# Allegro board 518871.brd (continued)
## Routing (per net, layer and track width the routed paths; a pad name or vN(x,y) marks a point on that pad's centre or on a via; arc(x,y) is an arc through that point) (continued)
H_DISPLAY_RSTN: length 40.9
  TOP w0.102: U27.Y4 55.68,86.9 55.68,90.58
  TOP w0.127: v1(85.69,95.12) 85.69,94.7 R444.1 ; v1(55.68,92.2) 55.68,90.58
  LY4 w0.133: v1(85.69,95.12) 85.69,94.58 85.22,94.11 78.11,94.11 77.85,93.85 75.82,93.85 75.18,94.49 70.87,94.49 68.83,92.46 64.9,92.46 64.64,92.2 v1(55.68,92.2)
  BOTTOM w0.127: v1(85.69,95.12) 85.69,96.65
H_DS90C189_RSTN: length 48.3
  TOP w0.127: U27.L3 v3(56.35,81.07) ; v1(97.66,87.38) R443.1
  LY3 w0.102: v3(56.35,81.07) 58.09,81.07
  LY3 w0.133: v1(97.66,87.38) 96.65,86.36 96.65,84.71 94.11,82.17 85.85,82.17 85.6,81.92 84.11,81.92 82.98,80.78 74.83,80.78 74.69,80.64 62.74,80.64 62.36,80.26 61.85,80.26 61.04,81.07 58.09,81.07
  BOTTOM w0.127: v1(97.66,87.38) 97.63,87.34 U77.52
H_EMU0: length 50.7
  TOP w0.102: 44.33,75.54 U27.C21
  TOP w0.127: v3(44,75.87) 44.33,75.54 ; v1(74.68,53.85) 74.25,53.42 J14.19
  LY3 w0.133: v3(44,75.87) 44.58,75.3 44.58,73.79 45.21,73.15 45.21,68.2 48.9,64.52 48.9,62.87 51.94,59.82 v1(51.94,59.44)
  LY4 w0.133: v1(51.94,59.44) 54.86,59.44 55.24,59.05 57.4,59.05 58.04,58.42 58.8,58.42 59.44,59.05 68.07,59.05 70.74,56.39 72.9,56.39 74.68,54.61 v1(74.68,53.85)
  BOTTOM w0.127: R310.2 75.18,52.83 75.18,53.34 v1(74.68,53.85)
H_EMU1: length 48.9
  TOP w0.102: 43.68,75.54 U27.C22
  TOP w0.127: v3(44,75.22) 43.68,75.54 ; J14.21 v1(73.75,53.09)
  LY3 w0.133: v1(51.98,58.29) 51.98,58.76 48.51,62.23 48.51,64.52 46.23,66.8 44.83,66.8 44,67.63 v3(44,75.22)
  LY4 w0.133: v1(51.98,58.29) 53.74,56.53 60.73,56.53 61.47,57.28 62.1,57.28 62.65,56.73 68.37,56.73 69.85,55.24 72.26,55.24 73.28,54.23 73.28,53.56 v1(73.75,53.09)
  BOTTOM w0.127: v1(73.75,53.09) 73.53,52.87 R311.2
H_EMU2: length 30.2
  TOP w0.127: v1(75.75,53.13) J14.13
  LY4 w0.133: v1(75.75,53.13) 75.75,53.14 75.18,53.71 75.18,54.61 72.64,57.15 70.61,57.15 68.24,59.52 v1(56.05,59.52)
  BOTTOM w0.127: R292.2 54.61,64.26 55.63,63.25 55.63,62.48 56.05,62.06 v1(56.05,59.52)
H_EMU3: length 47.7
  TOP w0.127: v1(48.64,67.44) 48.19,67.88 48.19,71.16 48.77,71.73 48.77,73.91 48.57,74.11 48.57,75.64 48.11,76.09 48.11,76.73 48.88,77.49 U27.F14 ; J14.17 v1(74.75,53.09)
  LY3 w0.133: v1(48.64,67.44) 48.64,65.41 49.4,64.64 49.4,63.12 52.32,60.2 54.36,60.2 v1(56.01,58.55)
  LY4 w0.133: v1(74.75,53.09) 74.21,53.63 74.21,54.14 74.21,54.15 74.21,54.31 72.52,56.01 70.48,56.01 67.78,58.72 59.86,58.72 59.18,58.04 57.66,58.04 57.15,58.55 v1(56.01,58.55)
H_EMU4: length 47.2
  TOP w0.102: 49.28,73.51 49.28,74.04 49.23,74.09 49.23,77.17 49.53,77.47 U27.F13
  TOP w0.127: J14.23 73.25,53.31 v1(73.79,53.85) ; v1(54.95,57.02) 54.74,57.24 54.74,63.12 51.94,65.91 50.8,65.91 49.53,67.18 49.53,67.69 49.28,67.95 49.28,73.51
  LY4 w0.133: v1(54.95,57.02) 60.61,57.02 61.38,57.78 67.94,57.78 70.1,55.63 72.39,55.63 73.79,54.23 v1(73.79,53.85)
H_EMU5: length 36.9
  TOP w0.127: U27.D8 v3(52.45,75.87) ; J14.25 v1(72.75,53.07)
  LY3 w0.133: v1(63.37,57.15) 62.74,57.78 61.72,57.78 59.31,60.2 59.31,66.42 55.17,70.56 55.17,71.45 52.83,73.79 52.83,75.49 v3(52.45,75.87)
  BOTTOM w0.127: v1(63.37,57.15) 63.88,56.64 69.17,56.64 v1(72.75,53.07)
H_EMU6: length 36.4
  TOP w0.102: U27.B7 53.75,74.57 53.75,73.51
  TOP w0.127: J14.27 72.25,53.33 v1(72.77,53.85) ; 53.75,73.51 53.75,73.14 57.15,69.74 57.15,68.58 60.58,65.15 60.58,59.94 61.47,59.06 61.47,57.66 61.72,57.4 v1(61.72,56.73)
  LY4 w0.133: v1(72.77,53.85) 71.75,54.86 69.47,54.86 67.94,56.39 62.06,56.39 v1(61.72,56.73)
H_EMU7: length 37.5
  TOP w0.127: J14.29 71.75,58.92 72.01,59.18 72.01,61.98 72.14,62.1 72.14,65.28 v1(71.63,65.79) ; U27.C7 v3(53.75,75.22)
  LY3 w0.133: v3(53.75,75.22) 53.76,74.13 59.05,68.83 59.69,68.83 62.74,65.79 v1(71.63,65.79)
H_EMU8: length 39.4
  TOP w0.127: J14.31 71.25,52.96 71.37,53.09 71.37,59.18 71.59,59.4 v1(71.59,64.77) ; v3(52.45,76.52) U27.E8
  LY3 w0.133: v1(71.59,64.77) 61.59,64.77 55.43,70.93 55.43,71.57 53.09,73.91 53.09,75.89 v3(52.45,76.52)
H_EMU9: length 34.5
  TOP w0.102: 53.1,73.51 53.1,74.57 U27.B8
  TOP w0.127: J14.33 70.75,52.93 70.74,52.95 v1(70.74,53.09) ; v1(60.45,58.29) 60.07,58.67 60.07,64.9 56.64,68.33 56.64,69.53 53.1,73.07 53.1,73.51
  BOTTOM w0.127: v1(70.74,53.09) 70.74,54.23 68.71,56.26 63.5,56.26 61.98,57.78 60.96,57.78 v1(60.45,58.29)
H_EMU10: length 35.5
  TOP w0.127: v1(70.25,53.85) J14.35 ; v3(52.45,75.22) 52.78,75.54 U27.C8
  LY3 w0.133: v1(59.73,57.53) 59.73,59.02 58.93,59.82 58.93,66.29 54.91,70.31 54.91,71.33 52.45,73.78 v3(52.45,75.22)
  BOTTOM w0.127: v1(70.25,53.85) 69.49,54.61 66.04,54.61 65.15,55.5 61.76,55.5 v1(59.73,57.53)
H_EMU11: length 35.6
  TOP w0.102: 52.45,73.51 52.45,74.57 U27.B9
  TOP w0.127: J14.37 v1(69.75,53.09) ; v1(59.82,56.11) 59.82,56.13 59.31,56.64 59.31,64.9 56.13,68.07 56.13,69.09 54.75,70.47 54.03,70.47 53.84,70.67 53.84,71.39 52.45,72.77 52.45,73.51
  BOTTOM w0.127: v1(59.82,56.11) 59.84,56.11 61.13,54.82 64.05,54.82 64.77,54.1 69.47,54.1 69.75,53.82 v1(69.75,53.09)
H_EMU12: length 33.7
  TOP w0.127: v1(62.87,53.09) 62.87,54.61 61.09,56.39 61.09,58.93 60.33,59.69 60.33,65.02 56.9,68.45 56.9,69.64 53.43,73.1 U27.A7 ; J14.39 v1(69.25,53.59)
  BOTTOM w0.127: v1(62.87,53.09) 63.37,53.59 v1(69.25,53.59)
H_EMU13: length 34.4
  TOP w0.127: U27.A9 52.13,72.53 52.83,71.83 52.83,70.87 53.48,70.22 54.14,70.22 55.5,68.86 55.5,68.33 58.97,64.86 v1(58.97,56.11) ; J14.41 v1(68.75,53.09)
  BOTTOM w0.127: v1(68.75,53.09) 68.24,52.58 62.48,52.58 58.97,56.1 v1(58.97,56.11)
H_EMU14: length 36.1
  TOP w0.127: J14.43 v1(68.25,49.28) ; v1(61.09,53.17) 61.09,55.12 60.71,55.5 60.71,57.36 59.69,58.38 59.69,64.88 56.39,68.18 56.39,69.42 52.78,73.03 U27.A8
  BOTTOM w0.127: v1(61.09,53.17) 62.06,52.2 66.29,52.2 68.25,50.24 v1(68.25,49.28)
H_EMU15: length 36.5
  TOP w0.127: v1(57.75,56.11) 57.28,56.58 57.28,63.25 52.58,67.94 52.58,68.71 52.32,68.96 50.93,68.96 50.55,69.34 50.55,71.4 50.83,71.68 U27.A11 ; J14.45 v1(67.75,49.91)
  BOTTOM w0.127: v1(57.75,56.11) 60.45,53.41 60.45,52.96 61.59,51.82 65.91,51.82 67.75,49.98 v1(67.75,49.91)
H_EMU16: length 40.3
  TOP w0.127: J14.47 v1(67.25,49.28) ; U27.F10 v3(51.15,77.17)
  LY3 w0.133: v1(56.1,62.74) 56.1,66.71 54.74,68.07 54.74,68.83 52.7,70.87 52.7,71.25 51.43,72.52 51.43,74.31 51.18,74.56 51.18,77.14 51.18,77.14 v3(51.15,77.17)
  BOTTOM w0.127: v1(56.1,62.74) 57.28,61.56 57.28,53.98 60.33,50.93 65.02,50.93 66.67,49.28 v1(67.25,49.28)
H_EMU17: length 35.2
  TOP w0.127: J14.49 v1(66.75,49.91) ; v1(59.94,53.09) 59.94,54.36 58.55,55.75 58.55,56.68 58.04,57.19 58.04,65.02 54.81,68.25 54.81,68.73 53.83,69.71 53.69,69.71 52.86,69.71 51.73,70.83 51.73,72.09 51.48,72.35 U27.A10
  BOTTOM w0.127: v1(66.75,49.91) 65.23,51.44 61.15,51.44 59.94,52.64 v1(59.94,53.09)
H_EMU18: length 32.4
  TOP w0.102: U27.B10 51.81,74.57 51.81,73.51
  TOP w0.127: v1(58.47,58.93) 58.47,64.98 55.17,68.27 55.17,68.73 53.94,69.96 53.59,69.96 53.58,69.96 53.23,69.96 52.58,70.61 52.58,71.62 51.81,72.39 51.81,73.51 ; v1(66.25,55.33) J14.51
  BOTTOM w0.127: v1(58.47,58.93) 59.14,58.93 60.66,57.4 61.72,57.4 63.25,55.88 65.7,55.88 v1(66.25,55.33)
H_EMU19: length 33.8
  TOP w0.127: v1(65.02,54.86) 65.75,54.14 J14.53 ; U27.E10 v3(51.8,76.52)
  LY3 w0.133: v3(51.8,76.52) 51.42,76.13 51.42,74.96 51.82,74.56 51.82,73.28 53.85,71.25 53.85,70.1 57.78,66.17 57.78,58.8 58.55,58.04 v1(58.55,57.49)
  BOTTOM w0.127: v1(58.55,57.49) 59.14,56.9 59.82,56.9 61.59,55.12 64.77,55.12 v1(65.02,54.86)
H_HDMI_CLKX: length 32.6
  TOP w0.112: U27.AE9 52.13,90.11 53.95,91.93 53.95,104.37 50.47,107.85 46.74,107.85 45.49,109.09 42.22,109.09 42.09,109.22 42.09,109.5 41.96,109.63 41.77,109.63 41.64,109.5 41.64,109.22 41.51,109.09 40.8,109.09 40.67,109.23 40.67,109.55 40.92,109.81 FL4.4
H_HDMI_CLKY: length 32.6
  TOP w0.112: U27.AD10 51.77,89.49 51.77,90.26 53.59,92.08 53.59,104.22 50.32,107.49 46.59,107.49 45.34,108.74 40.66,108.74 40.31,109.08 40.31,109.6 40.11,109.81 FL4.1
H_HDMI_DX0: length 31.2
  TOP w0.112: FL8.4 37.87,108.1 37.64,107.87 37.64,107.43 37.75,107.31 39.6,107.31 39.73,107.45 39.73,107.72 39.86,107.85 40.04,107.85 40.17,107.72 40.17,107.45 40.31,107.31 44.78,107.31 45.89,106.2 48.92,106.2 51.44,103.68 51.44,91.57 50.84,90.98 50.84,90.43 50.83,90.42 U27.AE11
H_HDMI_DX1: length 32
  TOP w0.102: 50.18,90.58 50.18,90.55 50.18,90.55 U27.AE12
  TOP w0.112: 50.18,90.58 50.18,92.09 50.42,92.33 50.42,98.83 43.33,105.92 33.91,105.92 33.66,106.17 33.66,106.73 33.79,106.86 34.05,106.86 34.16,106.97 34.16,107.2 34.05,107.31 33.69,107.31 33.58,107.42 33.58,107.87 33.81,108.1 FL7.4
H_HDMI_DX2: length 35
  TOP w0.102: 48.94,90.7 48.94,90.63 48.94,90.53 48.88,90.47 U27.AE14
  TOP w0.112: FL3.4 30.76,110.13 30.53,109.91 30.53,109.63 30.64,109.52 31,109.52 31.11,109.41 31.11,109.18 31,109.07 30.72,109.07 30.61,108.96 30.61,106.3 32.38,104.52 42.44,104.52 48.96,98 48.96,90.97 48.96,90.72 48.94,90.71 48.94,90.7
H_HDMI_DY0: length 31.3
  TOP w0.102: U27.AD12 50.48,89.5 50.48,90.58
  TOP w0.112: 50.48,90.58 50.48,91.13 51.08,91.72 51.08,103.54 48.77,105.84 45.75,105.84 44.63,106.96 37.61,106.96 37.29,107.28 37.29,107.87 37.06,108.1 FL8.1
H_HDMI_DY1: length 32
  TOP w0.102: 49.82,90.58 49.82,90.55 49.82,90.55 49.82,89.48 U27.AD13
  TOP w0.112: 49.82,90.58 49.82,92.24 50.06,92.48 50.06,98.68 43.19,105.56 33.76,105.56 33.3,106.02 33.3,106.87 33.22,106.95 33.22,107.87 32.99,108.1 FL7.1
H_HDMI_DY2: length 35
  TOP w0.102: U27.AD15 48.56,89.52 48.56,89.99 48.65,90.09 48.65,90.47 48.6,90.52 48.6,90.63 48.6,90.83 48.6,90.87
  TOP w0.112: 48.6,90.87 48.6,90.95 48.6,90.97 48.6,97.85 42.29,104.17 32.24,104.17 30.25,106.15 30.25,109.11 30.18,109.18 30.18,109.91 29.95,110.13 FL3.1
H_I2C1_SCL: length 277.1
  TOP w0.127: U602.5 39.87,49.27 v1(39.62,49.02) ; v1(11.56,111.51) U22.6 ; U78.19 24.36,54.08 24.64,54.36 24.89,54.36 v1(25.4,54.86) 25.4,61.34 25.15,61.59 v1(25.15,65.02) ; U27.G22 v3(43.35,77.82) ; U26.6 v1(48.01,122.42) ; U606.16 v1(123.32,112.91)
  LY4 w0.133: v1(123.32,112.91) 120.78,110.37 120.78,108.08 119,106.3 116.33,106.3 115.06,105.03 78.23,105.03 73.03,110.24 73.03,116.46 71.12,118.36 61.59,118.36 54.99,124.97 52.7,124.97 50.16,122.42 v1(48.01,122.42) 47.49,122.94 27.69,122.94 20.95,116.2 13.97,116.2 10.92,113.16 10.92,112.14 v1(11.56,111.51) 12.06,111 12.06,109.35 1.87,99.16 1.87,68.1 4.95,65.02 v1(25.15,65.02) 27.56,65.02 35.16,72.62 36.92,72.62 38.18,73.88 39.42,73.88 v3(43.35,77.82) ; v1(39.62,49.02) 37.51,49.02 37.16,49.37 37.16,50.12 37.59,50.55 37.59,57.78 36.84,58.54 29.08,58.54 v1(25.4,54.86)
  BOTTOM w0.127: R234.1 v1(11.56,111.51)
H_I2C1_SDA: length 277.2
  TOP w0.102: U27.G23 42.73,77.84 40.97,77.84
  TOP w0.127: v1(24.64,65.66) 24.64,54.91 v1(24.62,54.89) 23.86,54.13 U78.20 ; U602.6 v1(40.37,49.03) ; U606.15 v1(123.32,112.11) ; 40.97,77.84 40.12,77.84 38.73,76.45 36.07,76.45 31.11,71.5 v1(31.11,70.23) ; U22.5 v1(11.56,112.78) ; v1(47.24,122.43) 47.74,122.92 U26.5
  LY4 w0.133: v1(40.37,49.03) 39.79,48.45 37.53,48.45 36.83,49.15 36.83,50.42 37.08,50.67 37.08,54.1 34.54,56.64 34.54,57.66 34.04,58.17 29.84,58.17 26.04,54.36 25.15,54.36 v1(24.62,54.89) ; v1(31.11,70.23) 26.54,65.66 v1(24.64,65.66) 5.33,65.66 5.21,65.78 4.71,65.78 2.13,68.35 2.13,98.91 12.57,109.35 12.57,111.76 v1(11.56,112.78) 14.61,115.82 21.21,115.82 27.81,122.43 v1(47.24,122.43) 48.26,121.41 49.78,121.41 52.96,124.59 54.74,124.59 61.34,117.98 70.87,117.98 72.64,116.2 72.64,109.86 77.98,104.52 115.32,104.52 116.59,105.79 119.13,105.79 121.28,107.95 121.28,110.08 v1(123.32,112.11)
  BOTTOM w0.127: v1(11.56,112.78) R233.1
H_JTAG_RTCK: length 71.4
  TOP w0.127: v1(26.42,62.48) 26.42,70.99 R70.2 ; J14.7 77.25,53.37 v1(77.72,53.85)
  LY4 w0.133: v1(77.72,53.85) 77.72,53.98 72.26,59.44 69.6,59.44 68.71,60.33 49.53,60.33 48.64,61.21 27.69,61.21 v1(26.42,62.48)
H_JTAG_TCK: length 63.1
  TOP w0.127: v1(78.49,53.47) 78.49,53.09 78.25,52.85 J14.3 ; v3(44,79.77) U27.K21
  LY3 w0.133: v1(53.47,53.47) 51.56,55.37 51.56,58.55 48.13,61.98 48.13,64.39 46.48,66.04 43.69,66.04 43.05,66.67 43.05,74.42 42.8,74.68 42.8,78.56 v3(44,79.77)
  LY4 w0.133: v1(78.49,53.47) 78.49,53.09 77.85,52.45 54.48,52.45 v1(53.47,53.47)
  BOTTOM w0.127: R307.2 v1(78.49,53.47)
H_JTAG_TDI: length 90
  TOP w0.102: 40.97,80.77 41.15,80.77 41.42,81.04 42.73,81.04 U27.L23
  TOP w0.127: 40.97,80.77 39.37,80.77 38.1,79.5 35.03,79.5 31.98,76.45 27.81,76.45 25.78,74.42 v1(25.78,61.98) ; J14.5 v1(77.75,53.09)
  LY4 w0.133: v1(77.75,53.09) 77.3,53.53 77.3,53.89 72.14,59.05 69.34,59.05 68.45,59.94 49.28,59.94 48.39,60.83 26.92,60.83 v1(25.78,61.98)
H_JTAG_TDO: length 62.4
  TOP w0.127: J14.4 78.25,44.22 v1(78.99,43.47)
  LY3 w0.133: v1(31.75,65.79) 32.63,64.9 44.19,64.9 50.79,58.31 50.79,54.24 v1(51.94,53.09)
  BOTTOM w0.127: R264.2 v1(31.75,65.79) ; v1(51.94,53.09) 52.96,52.07 53.59,52.07 58.17,47.5 70.87,47.5 74.89,43.47 v1(78.99,43.47)
H_JTAG_TMS: length 88.8
  TOP w0.127: v1(78.99,44.2) 78.75,44.44 J14.2 ; v3(44,81.07) U27.L21
  LY3 w0.133: v1(29.84,68.07) 29.84,64.77 32.77,61.85 43.18,61.85 43.69,61.34 46.74,61.34 50.04,58.04 50.04,53.47 51.69,51.82 52.96,51.82 57.28,47.5 63.25,47.5 63.75,46.99 71.5,46.99 75.04,43.45 78.25,43.45 v1(78.99,44.2)
  LY4 w0.133: v1(29.84,68.07) 34.8,73.03 34.8,76.45 36.7,78.36 38.35,78.36 40.64,80.64 43.58,80.64 v3(44,81.07)
  BOTTOM w0.127: v1(78.99,44.2) 79.12,44.32 R328.2
H_JTAG_TRSTN: length 77.9
  TOP w0.127: v3(43.35,81.07) U27.L22
  LY3 w0.133: v1(52.07,53.98) 51.17,54.87 51.17,58.43 47.12,62.48 47.12,63.88 46.61,64.39 45.59,64.39 44.72,65.27 33.29,65.27 32.26,66.29 32.26,74.55 v1(32.77,75.06)
  LY4 w0.133: v3(43.35,81.07) 40.55,81.07 38.35,78.87 36.7,78.87 34.29,76.45 34.29,75.69 33.65,75.06 v1(32.77,75.06)
  BOTTOM w0.127: v1(52.07,53.98) 53.09,52.96 53.47,52.96 58.55,47.88 73.53,47.88 74.3,48.64 76.33,48.64
H_MCASP4_ACLKX: length 29.5
  TOP w0.127: R97.1 v1(43.05,64.39) ; v1(31.75,64.39) 31.75,62.48 27.72,58.46 27.72,52.62 26.55,51.44 U78.15
  LY3 w0.133: v1(31.75,64.39) v1(43.05,64.39)
H_MCASP4_AXR0: length 35.4
  TOP w0.102: 42.38,72.87 U27.A24
  TOP w0.127: U78.13 27.08,50.44 28.49,51.85 28.49,58.08 32.77,62.36 32.77,67.06 33.62,67.91 39.15,67.91 41.02,69.78 41.02,71.37 42.38,72.73 42.38,72.87
H_MCASP4_AXR1: length 40.9
  TOP w0.102: 43.03,73.51 43.03,73.81 43.33,74.12 43.33,75.89 U27.D23
  TOP w0.127: U78.18 26.14,52.93 26.67,53.47 v1(26.67,59.44) ; v1(42.42,60.2) 42.42,63.12 43.56,64.26 43.56,67.44 42.93,68.07 42.93,71.25 43.03,71.35 43.03,73.51
  LY4 w0.133: v1(42.42,60.2) 27.43,60.2 v1(26.67,59.44)
H_MCASP4_FSX: length 34.2
  TOP w0.102: 41.35,73.51 41.35,74.52 U27.B25
  TOP w0.127: 41.35,73.51 41.35,72.6 37.97,69.22 34.16,69.22 32.26,67.31 32.26,62.48 28.11,58.33 28.11,52.24 26.81,50.94 U78.14
H_MMC1_CLK: length 50
  TOP w0.127: R66.1 64.9,85.09 65.06,85.26 72.99,85.26 73.41,84.84 75.69,84.84 v1(75.95,85.09)
  LY3 w0.133: v1(107.31,92.71) 106.3,92.71 106.17,92.58 89.53,92.58 89.03,92.08 79.5,92.08 76.58,89.15 76.58,85.72 v1(75.95,85.09)
  BOTTOM w0.127: R406.1 v1(107.31,92.71) R226.2
H_MMC1_CMD: length 60
  TOP w0.127: U27.V4 v3(55.7,85.62)
  LY3 w0.102: v3(55.7,85.62) 56.06,85.98 58.09,85.98
  LY3 w0.133: v1(107.31,93.85) 106.68,93.85 105.79,92.96 89.28,92.96 88.77,92.46 78.49,92.46 75.31,89.28 75.31,85.72 74.42,84.84 72.39,84.84 71.35,85.88 58.19,85.88 58.09,85.98
  BOTTOM w0.127: R227.2 v1(107.31,93.85) R405.1
H_MMC1_D0: length 59.5
  TOP w0.127: U27.V3 v3(56.35,85.62)
  LY3 w0.102: v3(56.35,85.62) 58.09,85.62
  LY3 w0.133: v1(107.31,91.31) 106.43,92.2 89.79,92.2 89.28,91.69 80.14,91.69 77.85,89.41 77.85,85.98 75.78,83.91 72.43,83.91 70.72,85.62 58.09,85.62
  BOTTOM w0.127: R407.1 v1(107.31,91.31) R228.2
H_MMC1_D1: length 57.7
  TOP w0.102: U27.V2 56.99,85.6 58.09,85.6
  TOP w0.127: 58.09,85.6 61.59,85.6 61.85,85.85 75.56,85.85 75.69,85.72 v1(79.12,85.72)
  LY3 w0.133: v1(107.31,90.04) 107.06,90.3 96.65,90.3 96.27,89.92 86.74,89.92 85.47,91.19 80.9,91.19 79.12,89.41 v1(79.12,85.72)
  BOTTOM w0.127: R408.1 v1(107.31,90.04) R230.2
H_MMC1_D2: length 56.8
  TOP w0.102: 58.09,85.94 U27.W1
  TOP w0.127: v1(72.39,86.49) 70.48,86.49 70.12,86.12 61.61,86.12 61.43,85.94 60.17,85.94 60.17,85.94 58.09,85.94
  LY3 w0.133: v1(72.39,86.49) 73.41,87.5 73.41,89.15 77.47,93.22 88.14,93.22 88.65,93.73 104.65,93.73 v1(107.31,96.39)
  BOTTOM w0.127: R403.1 v1(107.31,96.39) R231.2
H_MMC1_D3: length 57.9
  TOP w0.102: U27.V1 58.09,85.29
  TOP w0.127: v1(74.04,85.34) 73.79,85.6 62.1,85.6 61.8,85.29 58.09,85.29
  LY3 w0.133: v1(74.04,85.34) 74.04,88.86 78.02,92.84 88.53,92.84 89.03,93.34 105.41,93.34 v1(107.31,95.25)
  BOTTOM w0.127: R229.2 v1(107.31,95.25) R404.1
H_MMC1_SDCD: length 59.3
  TOP w0.102: 58.09,84.33 55.05,84.33 U27.U5
  TOP w0.127: v1(80.26,85.34) 78.23,83.31 67.44,83.31 66.34,84.41 65.1,84.41 65.04,84.35 61.87,84.35 61.59,84.07 59.56,84.07 59.31,84.33 58.09,84.33
  LY3 w0.133: v1(107.31,88.77) 106.3,88.77 105.16,89.92 97.28,89.92 96.9,89.53 82.42,89.53 80.26,87.38 v1(80.26,85.34)
  BOTTOM w0.127: R411.1 v1(107.31,88.77) R410.2
H_NMIN_DSP: length 16.2
  TOP w0.102: U27.L24 42.06,80.42 40.97,80.42
  TOP w0.127: 40.97,80.42 39.4,80.42 38.1,79.12 35.43,79.12 31.75,75.44 29.59,75.44 R71.2
H_PMIC_INTN: length 138.5
  TOP w0.127: U27.AB10 v3(51.8,88.22) ; U602.19 38.87,54.85 v1(38.73,54.99)
  LY3 w0.133: v1(21.84,70.23) 21.84,63.25 v1(22.99,62.1)
  LY4 w0.133: v1(38.73,54.99) 38.73,57.28 37.21,58.8 26.29,58.8 v1(22.99,62.1) ; v3(51.8,88.22) 52.26,88.68 52.26,91.76 v1(52.7,92.2) 52.7,92.71 53.34,93.34 53.34,94.87 45.34,102.87 9.78,102.87 4.19,97.28 4.19,69.72 4.57,69.34 20.95,69.34 v1(21.84,70.23)
  BOTTOM w0.127: R236.1 v1(52.7,92.2)
H_PORZ: length 107.8
  TOP w0.127: U27.F19 45.95,77.17 45.95,72.62 44.2,70.87 44.2,70.1 45.47,68.83 45.47,66.67 47.53,64.61 v1(47.53,64.23) ; U40.3 93.87,48.78 92.46,47.37 92.46,47.12 TP40.1
  TOP w0.132: U602.16 v2(40.37,55.12) ; U602.2 v2(38.37,49.68)
  LY4 w0.133: TP40.1 90.17,44.83 65.53,44.83 62.99,47.37 56.9,47.37 56.39,46.86 53.47,46.86 50.8,49.53 50.8,56.77 48.39,59.18 41.4,59.18 40.37,58.15 v2(40.37,55.12) 38.37,53.12 v2(38.37,49.68)
  BOTTOM w0.127: v1(47.53,64.23) 47.53,61.5 44.45,58.42 41.27,58.42 41.02,58.17 41.02,57.02 R602.2
  BOTTOM w0.132: R602.2 40.26,55.5 40.37,55.39 v2(40.37,55.12)
H_RSTOUTN: length 43.6
  TOP w0.127: U27.E20 45.32,76.5 45.32,73.74 45.19,73.61 45.19,72.87 43.69,71.37 43.69,69.6 44.29,68.99 44.29,67.67 44.96,67 R104.2 TP36.1
  LY4 w0.133: TP36.1 47.5,62.48 54.74,62.48 55.5,63.25 57.28,63.25 57.4,63.12 69.09,63.12 69.72,62.48 v1(70.23,62.48)
  BOTTOM w0.14: U54.1 71.87,61.36 70.74,62.48 v1(70.23,62.48)
H_TAS2505_RSTN: length 44.6
  TOP w0.102: U27.F24 42.19,77.49 41.88,77.19 40.97,77.19
  TOP w0.127: v1(29.97,61.72) 30.99,62.74 30.99,68.45 32.38,69.85 32.38,72.39 36.2,76.2 38.99,76.2 39.98,77.19 40.97,77.19 ; U78.2 v1(19.95,52.44)
  BOTTOM w0.127: v1(29.97,61.72) 28.19,61.72 27.94,61.47 22.1,61.47 18.92,58.29 18.92,53.47 v1(19.95,52.44) 20.56,52.44 R437.1
H_UART3_RXD_BOOT: length 115.5
  TOP w0.127: U27.N22 v3(43.35,81.72)
  LY4 w0.102: v3(43.35,81.72) 43.04,81.41 40.97,81.41
  LY4 w0.133: v1(25.27,116.84) 23.88,115.44 15.88,115.44 13.84,113.41 13.84,108.08 13.21,107.44 11.18,107.44 2.39,98.66 2.39,68.6 4.95,66.04 22.86,66.04 23.62,66.8 27.05,66.8 32.26,72.01 32.26,75.44 36.07,79.25 38.23,79.25 40.39,81.41 40.97,81.41
  BOTTOM w0.127: R232.1 v1(25.27,116.84)
H_UART3_TXD_BOOT: length 108.9
  TOP w0.102: 40.97,81.23 41.46,81.72 42.06,81.72 42.06,81.72 U27.N24
  TOP w0.127: v2(21.06,114.95) 20.7,115.32 R56.2 ; v1(38.1,80.26) 38.99,81.15 40.89,81.15 40.97,81.23
  LY4 w0.133: v1(38.1,80.26) 37.47,79.63 35.94,79.63 31.88,75.56 31.88,72.14 26.9,67.16 23.47,67.16 22.71,66.4 5.13,66.4 2.65,68.87 2.65,98.41 11.3,107.06 13.5,107.06 14.22,107.79 14.22,113.03 15.49,114.3 20.41,114.3 v2(21.06,114.95)
  BOTTOM w0.127: U52.2 v2(21.06,114.95)
H_XREF_CLK3: length 32.4
  TOP w0.127: U78.16 26.28,51.94 27.34,53 27.34,60.87 28.07,61.59 28.07,71.12 29.84,72.9 31.73,72.9 35.14,76.31 35.26,76.39 36.22,77.34 R75.2
HDMI_CEC_A: length 46.3
  TOP w0.102: U27.AB1 58.09,87.89
  TOP w0.127: 58.09,87.89 60.46,87.89 61.59,89.03 v1(61.59,109.35) ; v1(47.17,117.35) U17.24
  LY4 w0.133: v1(61.59,109.35) 55.75,109.35 52.58,112.52 52.58,115.32 50.55,117.35 v1(47.17,117.35)
HDMI_CEC_B: length 14
  TOP w0.127: R27.1 44.49,113.67 44.78,113.37 45.32,113.37 v1(45.42,113.28) 45.72,113.28 45.77,113.34 U17.6
  TOP w0.14: v1(38.72,118) P1.13 38.72,119.52
  LY4 w0.133: v1(38.72,118) 39.34,118.62 40.01,118.62 41.91,116.71 41.91,115.7 44.28,113.33 45.37,113.33 v1(45.42,113.28)
HDMI_DSCL: length 117.2
  TOP w0.127: U17.1 v1(46.41,115.9)
  LY4 w0.133: v1(28.96,71.12) 26.04,68.2 4.06,68.2 3.17,69.09 3.17,97.92 11.56,106.3 42.16,106.3 46.74,110.87 46.74,115.57 v1(46.41,115.9)
  BOTTOM w0.127: 45.85,116.46 v1(46.41,115.9) ; R265.1 33.27,72.14 32.51,71.37 29.21,71.37 v1(28.96,71.12)
HDMI_DSDA: length 116.6
  TOP w0.127: U17.2 45.84,114.94 v1(45.47,115.32)
  LY4 w0.133: v1(29.59,70.61) 26.8,67.82 4.08,67.82 2.91,68.98 2.91,98.16 11.43,106.68 40.86,106.68 45.97,111.8 45.97,114.81 v1(45.47,115.32)
  BOTTOM w0.127: v1(45.47,115.32) 45.59,115.19 R215.1 ; v1(29.59,70.61) 29.97,70.99 32.89,70.99 33.15,71.25 R266.1
HDMI_HPD: length 52.8
  TOP w0.102: 58.09,87.24 U27.AA1
  TOP w0.127: R25.1 43.05,116.59 v1(43.69,117.22) ; v1(62.1,109.98) 62.1,108.84 61.85,108.58 61.85,88.77 60.71,87.63 58.55,87.63 58.16,87.24 58.09,87.24
  LY4 w0.133: v1(62.1,109.98) 55.75,109.98 53.09,112.65 53.09,115.32 50.42,117.98 44.45,117.98 v1(43.69,117.22)
HDMI_HPD_B: length 22.3
  TOP w0.127: U17.9 45.84,112.13 45.59,111.89 v1(44.83,111.89) 44.32,111.38 R31.2 R32.1
  TOP w0.14: P1.19 v1(41.72,121.03)
  LY4 w0.133: v1(44.83,111.89) 43.56,111.89 43.18,111.51 41.02,111.51 37.85,114.68 37.85,118.49 39.24,119.89 40.58,119.89 v1(41.72,121.03)
HDMI_SCL_B: length 11.9
  TOP w0.127: R28.1 v1(44.83,112.9) 45.2,112.9 45.24,112.86 45.68,112.86 45.75,112.94 U17.7
  TOP w0.14: v1(39.72,117.98) P1.15 39.72,119.52
  LY4 w0.133: v1(39.72,117.98) 40.13,117.98 41.53,116.59 41.53,115.57 44.2,112.9 v1(44.83,112.9)
HDMI_SDA_B: length 14.2
  TOP w0.127: R30.1 44.2,112.14 44.45,112.39 45.38,112.39 v1(45.42,112.36) 45.43,112.36 45.61,112.53 U17.8
  TOP w0.14: v1(40.22,116.97) P1.16 40.22,119.52
  LY4 w0.133: v1(45.42,112.36) 43.09,112.36 42.04,113.41 41.4,113.41 39.62,115.19 39.62,116.37 v1(40.22,116.97)
HDMI_TX0+: length 10.5
  TOP w0.102: P1.7 35.72,119.52
  TOP w0.112: FL8.2 37.06,110.34 37.29,110.57 37.29,111.3 U9.1 37.26,112 37.26,115.01 36.04,116.23 36.04,118.19 35.72,118.51 P1.7
HDMI_TX0-: length 10.5
  TOP w0.102: P1.9 36.72,119.52
  TOP w0.112: P1.9 36.72,118.51 36.4,118.19 36.4,116.38 37.62,115.16 37.62,112.05 U10.1 37.64,111.3 37.64,110.57 37.87,110.34 FL8.3
HDMI_TX1+: length 10.5
  TOP w0.102: 34.22,119.52 P1.4
  TOP w0.112: P1.4 34.22,118.46 34.54,118.14 34.54,116.59 33.22,115.27 33.22,112.02 U7.1 33.22,111.3 33.22,110.57 32.99,110.34 FL7.2
HDMI_TX1-: length 10.5
  TOP w0.102: 35.22,119.52 P1.6
  TOP w0.112: P1.6 35.22,118.4 34.9,118.08 34.9,116.44 33.58,115.12 33.58,112.02 U8.1 33.58,111.3 33.58,110.57 33.81,110.34 FL7.3
HDMI_TX2+: length 9.1
  TOP w0.102: P1.1 32.72,119.52
  TOP w0.112: FL3.2 29.95,112.37 30.18,112.6 30.18,113.21 U3.1 30.2,113.96 30.2,114.71 33.02,117.53 33.02,118.16 32.72,118.47 P1.1
HDMI_TX2-: length 9.1
  TOP w0.102: P1.3 33.72,119.52
  TOP w0.112: P1.3 33.72,118.49 33.38,118.15 33.38,117.38 30.56,114.56 30.56,113.9 U4.1 30.53,113.21 30.53,112.6 30.76,112.37 FL3.3
HDMI_TXC+: length 9.1
  TOP w0.102: 37.22,119.52 P1.10
  TOP w0.112: P1.10 37.22,118.51 37.54,118.19 37.54,117.2 40.36,114.38 40.36,113.96 U5.1 40.34,113.21 40.34,112.6 40.11,112.37 FL4.2
HDMI_TXC-: length 9.1
  TOP w0.102: 38.22,119.52 P1.12
  TOP w0.112: FL4.3 40.92,112.37 40.69,112.6 40.69,113.21 U6.1 40.72,113.9 40.72,114.52 37.9,117.34 37.9,118.09 38.22,118.41 P1.12
LED_K1: length 34.3
  TOP w2.032: D26.1 J24.1
  BOTTOM w2.032: R625.1 125.09,111.51 123.83,110.24 123.83,104.78 123.44,104.39 123.44,84.2 J24.1
LED_K2: length 44.8
  TOP w2.032: D27.1 124.43,74.17 J24.4
  BOTTOM w2.032: J24.4 123.06,74.19 120.9,76.35 120.9,105.66 121.41,106.17 R626.1
LP87523_REGEN_3V3: length 144.1
  TOP w0.127: v1(41.02,54.99) 40.87,54.84 U602.15 ; U42.6 72,27.81 73.15,28.96 73.15,31.75 ; 73.15,31.75 74.42,31.75 75.44,32.77 75.44,39.62 72.52,42.55 65.41,42.55 v1(63.12,44.83) 63.12,46.35 61.59,47.88 61.59,49.28 63.5,51.18 63.5,54.23 68.83,59.56 68.83,65.02 72.26,68.45 v1(72.26,71.88) ; 73.15,31.75 72.77,32.13 70.48,32.13 70.23,32.38 70.23,33.66 70.36,33.79 U601.3 ; U605.3 71.57,103.06 70.74,102.23 70.74,99.06 71.5,98.3 75.18,98.3 75.82,97.66 75.82,96.65 76.33,96.14 Q600.2 76.33,95.12 75.95,94.74 74.3,94.74 73.51,93.95 U604.3 72.76,93.1 v1(73.28,92.58)
  LY4 w0.133: v1(63.12,44.83) 62.87,44.58 58.42,44.58 56.52,46.48 53.09,46.48 50.42,49.15 50.42,56.52 48.13,58.8 41.78,58.8 41.02,58.04 v1(41.02,54.99)
  BOTTOM w0.127: R603.2 40.89,54.86 v1(41.02,54.99) ; v1(73.28,92.58) 73.28,89.79 73.03,89.53 73.03,72.64 v1(72.26,71.88)
MDIO_MDCLK: length 67.1
  TOP w0.127: U27.D10 v3(51.8,75.87) ; U40.1 92.87,49.43 v1(92.46,49.02)
  LY3 w0.133: v1(56.26,51.05) 56.26,50.16 58.17,48.26 63.75,48.26 64.22,47.79 84.5,47.79 84.84,48.13 89.28,48.13 90.17,49.02 v1(92.46,49.02)
  BOTTOM w0.127: v1(56.26,51.05) 56.26,55.5 56.43,55.66 56.43,56.86 55.12,58.17 55.12,61.98 54.61,62.48 54.61,63.12 52.58,65.15 52.58,71.74 51.44,72.88 51.44,75.5 v3(51.8,75.87)
MDIO_MDIO: length 65.1
  TOP w0.127: U27.C10 v3(51.8,75.22) ; U40.36 v1(91.22,50.7)
  LY3 w0.133: v1(91.22,50.7) 90.55,50.04 87.76,50.04 86.23,48.51 84.58,48.51 84.29,48.22 64.56,48.22 64.14,48.64 58.67,48.64 v1(56.9,50.42)
  BOTTOM w0.102: 51.8,73.51 v3(51.8,75.22)
  BOTTOM w0.127: 51.8,73.51 51.8,73.16 52.83,72.14 52.83,65.53 55.12,63.25 55.12,62.48 55.5,62.1 55.5,58.29 56.9,56.9 v1(56.9,50.42) ; v1(91.22,50.7) 91.19,50.73 R344.2
MMC2_CLK: length 34.3
  TOP w0.127: R99.1 62.74,65.91 62.74,61.51 62.46,61.24 62.12,61.24 61.98,61.09 61.98,60.88 62.12,60.73 62.46,60.73 62.61,60.58 62.61,60.37 62.46,60.22 62.12,60.22 61.98,60.07 61.98,59.86 62.12,59.71 62.46,59.71 v1(64.9,57.28)
  LY3 w0.133: v1(64.9,57.28) 68.96,57.28 69.34,56.9 v1(80.01,56.9)
  BOTTOM w0.127: R300.2 R299.1 v1(80.01,56.9)
MMC2_CMD: length 44.8
  TOP w0.127: U31.P5 v1(79.77,57.74) ; v1(61.98,58.29) 61.98,59.05 60.83,60.2 60.83,65.28 57.4,68.71 57.4,69.85 54.08,73.17 U27.A6
  LY3 w0.133: v1(79.77,57.74) 79.22,58.29 72.39,58.29 71.12,59.56 65.37,59.56 65.21,59.41 65.21,58.45 65.05,58.29 64.83,58.29 64.68,58.45 64.68,59.41 64.52,59.56 64.3,59.56 64.14,59.41 64.14,58.45 63.99,58.29 63.77,58.29 63.61,58.45 63.61,59.41 63.45,59.56 63.23,59.56 63.08,59.41 63.08,58.45 62.92,58.29 v1(61.98,58.29)
  BOTTOM w0.127: v1(79.77,57.74) 79.81,57.78 R295.2
MMC2_DAT0: length 44.2
  TOP w0.127: U31.K2 v1(76.77,61.74) 75.03,61.74 74.17,62.61 74.17,63.08 74.3,63.2 75.8,63.2 75.95,63.35 75.95,63.56 75.8,63.71 74.3,63.71 74.17,63.84 74.17,64.09 74.3,64.22 75.8,64.22 75.95,64.37 75.95,65.66 75.54,66.06 75.54,68.05 75.39,68.2 75.18,68.2 75.04,68.05 75.04,66.06 74.89,65.91 v1(73.85,65.91) ; U27.D7 v3(53.75,75.87)
  LY3 w0.133: v1(73.85,65.91) 73.47,66.29 62.74,66.29 59.81,69.22 59.18,69.22 54.17,74.23 54.17,75.45 v3(53.75,75.87)
  BOTTOM w0.127: v1(76.77,61.74) 76.75,61.72 R273.2
MMC2_DAT1: length 44.6
  TOP w0.102: 54.41,75.87 v3(54.4,75.87)
  TOP w0.127: U31.N2 v1(76.77,58.74) 73.46,58.74 73.03,59.18 73.03,59.98 73.17,60.13 75.18,60.13 75.31,60.26 75.31,60.45 75.12,60.64 73.17,60.64 73.03,60.79 73.03,61.04 73.17,61.19 73.91,61.19 74.04,61.32 74.04,61.57 73.91,61.7 73.17,61.7 72.52,62.36 72.52,62.61 72.67,62.76 73.13,62.76 73.28,62.91 73.28,63.12 73.13,63.27 72.67,63.27 72.52,63.42 72.52,63.63 72.67,63.78 73.13,63.78 73.28,63.92 73.28,64.14 73.13,64.28 72.67,64.28 72.52,64.43 72.52,66.55 72.22,66.84 v1(71.63,66.84) ; U27.C6 54.41,75.87
  LY3 w0.133: v1(71.63,66.84) 71.6,66.81 62.73,66.81 59.94,69.6 59.31,69.6 54.4,74.5 54.4,75.87 v3(54.4,75.87)
  BOTTOM w0.127: R271.2 76.71,58.8 v1(76.77,58.74)
MMC2_DAT2: length 45.1
  TOP w0.127: v1(61.98,63.88) 61.98,64.9 57.91,68.96 57.91,70.06 54.73,73.24 U27.A5 ; U31.K3 v1(77.77,61.74)
  LY3 w0.133: v1(77.77,61.74) 77.28,62.23 73.49,62.23 73.33,62.39 73.33,63.72 73.18,63.88 72.96,63.88 72.8,63.72 72.8,62.39 72.64,62.23 72.42,62.23 72.27,62.39 72.27,63.72 72.11,63.88 71.89,63.88 71.73,63.72 71.73,62.39 71.58,62.23 71.25,62.23 70.4,63.08 67.64,63.08 67.49,63.23 67.49,64.11 67.33,64.26 67.11,64.26 66.96,64.11 66.96,63.23 66.8,63.08 66.58,63.08 66.42,63.23 66.42,64.11 66.27,64.26 66.04,64.26 65.89,64.11 65.89,63.23 65.73,63.08 65.51,63.08 65.35,63.23 65.35,64.11 65.2,64.26 64.98,64.26 64.82,64.11 64.82,63.23 64.67,63.08 64.43,63.08 64.26,63.25 63.75,63.25 63.59,63.4 63.59,64.11 63.44,64.26 63.22,64.26 63.06,64.11 63.06,63.4 62.9,63.25 62.61,63.25 v1(61.98,63.88)
  BOTTOM w0.127: R269.2 77.79,61.72 v1(77.77,61.74)
MMC2_DAT3: length 43.9
  TOP w0.102: U27.B6 54.4,74.57 54.4,73.51
  TOP w0.127: v1(61.34,61.72) 61.34,65.15 57.66,68.83 57.66,69.95 54.4,73.21 54.4,73.51 ; U31.N3 v1(77.77,58.74)
  LY3 w0.133: v1(61.34,61.72) 61.34,61.11 61.18,60.95 60.1,60.95 59.94,60.8 59.94,60.58 60.1,60.42 61.18,60.42 61.34,60.26 61.34,59.44 61.47,59.31 62.23,59.31 62.93,60.01 62.93,61.57 63.08,61.72 63.31,61.72 63.46,61.57 63.46,60.48 63.62,60.33 65.02,60.33 65.91,61.21 68.58,61.21 69.72,60.07 71.5,60.07 72.9,58.67 74.8,58.67 75.31,59.18 77.33,59.18 v1(77.77,58.74)
  BOTTOM w0.127: R291.2 77.83,58.8 v1(77.77,58.74)
MMC2_DAT4: length 45.2
  TOP w0.127: U31.N8 v1(83.77,58.74) ; v1(66.04,58.29) 66.29,58.55 66.29,58.92 65.91,59.3 65.61,59.3 64.79,58.48 64.58,58.48 64.43,58.63 64.43,58.84 64.98,59.39 64.98,59.6 64.83,59.75 64.62,59.75 64.07,59.2 63.86,59.2 63.12,59.94 63.12,66.5 58.38,71.25 57.44,71.25 55.92,72.77 55.92,72.79 55.38,73.33 U27.A4
  LY3 w0.133: v1(66.04,58.29) 68.96,58.29 69.72,57.53 76.2,57.53 76.41,57.32 80.43,57.32 81.41,58.29 82.55,58.29 83,58.74 v1(83.77,58.74)
  BOTTOM w0.127: R289.2 83.59,58.93 v1(83.77,58.74)
MMC2_DAT5: length 43.5
  TOP w0.127: U31.K8 v1(83.77,61.74) ; U27.E7 v3(53.75,76.52)
  LY3 w0.133: v3(53.75,76.52) 53.38,76.15 53.38,74 55.75,71.63 55.75,71.12 61.59,65.28 73.72,65.28 73.88,65.12 73.88,63.78 74.03,63.63 74.26,63.63 74.41,63.78 74.41,65.12 74.57,65.28 74.8,65.28 76.71,63.37 78.11,63.37 79.76,61.72 83.75,61.72 v1(83.77,61.74)
  BOTTOM w0.127: v1(83.77,61.74) 83.62,61.59 R272.2
MMC2_DAT6: length 43.9
  TOP w0.127: U31.N9 v1(84.78,58.74) ; v1(62.48,67.82) 64.77,65.53 v1(64.77,61.21) ; U27.D6 v3(54.4,76.52)
  LY3 w0.133: v3(54.4,76.52) 54.42,76.52 54.86,76.07 54.86,75.69 54.68,75.51 54.68,74.73 59.44,69.98 60.07,69.98 61.85,68.2 62.1,68.2 v1(62.48,67.82) ; v1(84.78,58.74) 83.95,59.56 81.92,59.56 81.16,60.32 76.59,60.32 76.46,60.45 70.1,60.45 68.83,61.72 65.28,61.72 v1(64.77,61.21)
  BOTTOM w0.127: R270.2 84.84,58.67 v1(84.78,58.74)
MMC2_DAT7: length 43.4
  TOP w0.102: 55.05,75.22 v3(55.05,75.22) 55.05,75.22
  TOP w0.127: U27.C5 v3(55.05,75.22) ; U31.K9 v1(84.78,61.74)
  LY3 w0.133: v3(55.05,75.22) 55.05,74.87 59.56,70.36 60.2,70.36 61.98,68.58 65.02,68.58 66.34,67.27 70.82,67.27 71.5,67.94 73.78,67.94 73.94,68.1 73.94,68.8 74.1,68.96 74.32,68.96 74.47,68.8 74.47,68.1 74.63,67.94 74.85,67.94 75.01,68.1 75.01,68.8 75.16,68.96 75.38,68.96 75.54,68.8 75.54,68.1 75.7,67.94 75.95,67.94 76.2,67.69 76.2,64.52 76.96,63.75 78.49,63.75 80.01,62.23 84.29,62.23 v1(84.78,61.74)
  BOTTOM w0.127: R268.2 84.8,61.72 v1(84.78,61.74)
MMC_PWR_ON: length 72.6
  TOP w0.102: U27.Y2 56.98,86.89 58.09,86.89
  TOP w0.127: v1(67.56,91.31) 66.93,91.31 63.67,88.05 62.56,88.05 61.79,87.29 58.56,87.29 58.17,86.89 58.09,86.89 ; R412.2 v1(111.76,85.34) 111.25,84.83 U70.3
  LY3 w0.133: v1(67.56,91.31) 74.42,91.31 76.71,93.6 85.09,93.6 85.64,94.15 103.8,94.15 106.93,97.28 v1(109.86,97.28)
  LY4 w0.133: v1(109.86,97.28) 110.74,96.39 110.74,87.76 111.12,87.38 111.12,85.98 v1(111.76,85.34)
NOT_GP6_11/EHRPWM2B: length 23.2
  TOP w0.127: Q602.3 108.85,98.92 v1(109.09,98.68)
  LY4 w0.133: v1(109.09,98.68) 109.09,88.9 106.93,86.74 106.93,80.39 J1.1
  BOTTOM w0.127: R619.2 109.22,98.81 v1(109.09,98.68)
NTRST: length 3.9
  TOP w0.127: v1(77.09,49.66) 76.75,50 J14.9
  BOTTOM w0.127: RJ26.3 v1(77.09,49.66) 77.22,49.78 R312.2
PMIC_REGEN_LP87523: length 34.9
  TOP w0.127: U602.7 v1(40.87,49.68)
  TOP w0.203: U18.21 v1(36.19,21.34)
  LY4 w0.133: TP12.1 37.72,32.51 38.1,32.13 v1(38.1,29.97) 38.1,27.43 37.34,26.67 37.34,22.49 v1(36.19,21.34)
  BOTTOM w0.127: v1(38.1,29.97) 37.72,30.35 R433.2 ; TP12.1 38.1,35.94 38.1,36.83 40.86,39.59 40.86,48.18 40.87,48.2 v1(40.87,49.68) 40.87,50.53 R604.2
  BOTTOM w0.203: R217.1 36.2,21.34 v1(36.19,21.34)
RXEIN0+: length 8.2
  BOTTOM w0.112: U77.39 91.33,89.6 91.41,89.69 91.41,91.19 90.58,92.02 90.58,93.85 92.26,95.54 92.26,96.05 92.19,96.13 92.19,96.65
RXEIN0-: length 8.2
  BOTTOM w0.112: U77.40 91.83,89.66 91.77,89.72 91.77,91.33 90.93,92.17 90.93,93.71 92.61,95.39 92.61,96.05 92.69,96.13 92.69,96.65
RXEIN1+: length 8.2
  BOTTOM w0.112: U77.37 90.33,89.61 90.4,89.68 90.4,90.81 89.31,91.9 89.31,94.16 90.76,95.61 90.76,96.05 90.69,96.13 90.69,96.65
RXEIN1-: length 8.2
  BOTTOM w0.112: U77.38 90.83,89.66 90.75,89.73 90.75,90.95 89.66,92.04 89.66,94.01 91.11,95.46 91.11,96.05 91.19,96.13 91.19,96.65
RXEIN2+: length 8
  BOTTOM w0.112: U77.35 89.33,90.08 89.4,90.15 89.4,90.41 88.3,91.51 88.3,94.7 89.26,95.66 89.26,96.58 89.18,96.65
RXEIN2-: length 8
  BOTTOM w0.112: U77.36 89.83,90.08 89.75,90.15 89.75,90.56 88.65,91.66 88.65,94.55 89.61,95.51 89.61,96.57 89.68,96.64 89.68,96.65
RXEIN3+: length 11.2
  BOTTOM w0.112: U77.30 86.4,87.84 85.75,88.49 85.75,90.83 87.12,92.2 87.12,94.89 87.76,95.53 87.76,96.05 87.69,96.13 87.69,96.65
RXEIN3-: length 11.2
  BOTTOM w0.112: 88.19,96.65 88.19,96.13 88.11,96.05 88.11,95.38 87.47,94.74 87.47,92.05 86.11,90.68 86.11,89.98 86.24,89.84 86.66,89.84 86.79,89.71 86.79,89.53 86.66,89.4 86.24,89.4 86.11,89.27 86.11,89.03 86.29,88.84 U77.32
RXOCLKIN+: length 7.9
  BOTTOM w0.112: 95.19,96.65 95.19,96.13 95.26,96.05 95.26,94.16 93.4,92.3 93.4,90.15 93.32,90.08 U77.43
RXOCLKIN-: length 7.9
  BOTTOM w0.112: U77.44 93.82,90.08 93.75,90.15 93.75,92.15 95.62,94.02 95.62,96.05 95.69,96.13 95.69,96.65
RXOIN0+: length 10.3
  TOP w0.112: v1(99.56,95.25) 99.72,95.09 99.72,92.35 97.31,89.94 97.31,89.13 97.41,89.03 v1(97.41,88.52)
  BOTTOM w0.112: 99.69,96.65 99.69,95.38 v1(99.56,95.25) ; v1(97.41,88.52) 97.23,88.34 U77.50
RXOIN0-: length 10.2
  TOP w0.112: v1(97.79,89.28) 97.66,89.41 97.66,89.79 100.08,92.2 100.08,94.88 v1(100.44,95.25)
  BOTTOM w0.112: v1(100.44,95.25) 100.05,95.64 100.05,95.98 100.19,96.13 100.19,96.65 ; v1(97.79,89.28) 97.44,88.93 97.24,88.93 97.15,88.84 U77.49
RXOIN1+: length 9.5
  TOP w0.112: v1(95.63,91.31) 95.89,91.05 96.26,91.05 98.3,93.09 98.3,94.48 v1(98.03,94.74)
  BOTTOM w0.112: 98.19,96.65 98.19,96.13 98.27,96.05 98.27,94.98 v1(98.03,94.74) ; v1(95.63,91.31) 96.04,90.9 96.04,90.2 95.82,89.98 U77.48
RXOIN1-: length 9.4
  TOP w0.112: v1(95.63,90.43) 95.87,90.2 96.26,90.2 96.42,90.36 96.42,90.71 98.65,92.94 98.65,94.48 v1(98.92,94.74)
  BOTTOM w0.112: v1(98.92,94.74) 98.63,95.03 98.63,96.06 98.69,96.13 98.69,96.65 ; U77.47 95.32,90.12 v1(95.63,90.43)
RXOIN2+: length 9.2
  TOP w0.112: v1(96.51,95.25) 96.77,94.99 96.77,94.83 96.77,94.11 94.86,92.2 94.86,91.24 94.78,91.16 94.62,91.16 v1(94.36,91.42)
  BOTTOM w0.112: v1(96.51,95.25) 96.76,95.5 96.76,96.05 96.69,96.13 96.69,96.65 ; U77.46 94.82,90.96 v1(94.36,91.42)
RXOIN2-: length 9.2
  TOP w0.112: v1(97.39,95.25) 97.13,94.99 97.13,94.68 97.13,93.96 95.22,92.05 95.22,90.58 94.96,90.32 94.58,90.32 v1(94.36,90.54)
  BOTTOM w0.112: v1(97.39,95.25) 97.12,95.53 97.12,96.05 97.19,96.13 97.19,96.65 ; v1(94.36,90.54) 94.32,90.51 U77.45
RXOIN3+: length 8.2
  BOTTOM w0.112: 93.69,96.65 93.69,96.13 93.76,96.05 93.76,95.38 91.82,93.44 91.82,92.23 92.38,91.67 92.38,89.66 92.32,89.6 U77.41
RXOIN3-: length 8.2
  BOTTOM w0.112: 94.19,96.65 94.19,96.13 94.12,96.05 94.12,95.23 92.18,93.29 92.18,92.37 92.74,91.82 92.74,89.75 92.82,89.66 U77.42
SPK_N: length 107.1
  TOP w0.127: v1(22.87,48.77) U78.9
  LY4 w0.254: v1(22.87,48.77) 23.63,49.53 25.15,49.53 25.78,48.9 25.78,47.84 32.35,41.27 98.55,41.27 112.52,55.24 117.86,55.24 J17.8
SPK_P: length 104.8
  TOP w0.127: U78.12 24.36,49.3 v1(24.89,48.77)
  LY4 w0.254: v1(24.89,48.77) 24.89,47.88 32,40.77 98.81,40.77 112.65,54.61 117.86,54.61 118.52,53.95 J17.7
SWP1: length 2
  TOP w0.127: SW1.1 v1(81.03,86.36)
  BOTTOM w0.127: R258.2 v1(81.03,86.36)
SWP2: length 2
  TOP w0.127: SW1.2 v1(79.76,86.36)
  BOTTOM w0.127: R254.2 v1(79.76,86.36)
SWP3: length 2
  TOP w0.127: SW1.3 v1(78.49,86.36)
  BOTTOM w0.127: R250.2 v1(78.49,86.36)
SWP4: length 2
  TOP w0.127: SW1.4 v1(77.22,86.36)
  BOTTOM w0.127: R248.2 v1(77.22,86.36)
SWP5: length 2
  TOP w0.127: SW1.5 v1(75.95,86.36)
  BOTTOM w0.127: R244.2 v1(75.95,86.36)
SWP6: length 2
  TOP w0.127: SW1.6 v1(74.68,86.36)
  BOTTOM w0.127: R240.2 v1(74.68,86.36)
TRD1_N: length 3.9
  TOP w0.112: C233.1 R449.1 116.1,51.69 J17.2
TRD1_P: length 3.8
  TOP w0.112: J17.1 116.15,50.04 R450.1 C232.1
TRD_N: length 7.2
  TOP w0.112: U40.13 98.26,52.2 98.33,52.13 100.14,52.13 101.17,51.1 103.56,51.1 104.08,51.63 L44.3
TRD_P: length 7.2
  TOP w0.112: U40.12 98.26,51.7 98.33,51.78 99.99,51.78 101.02,50.75 103.53,50.75 104.05,50.23 L44.4
TRSTPD: length 4.2
  TOP w0.127: J14.8 v1(77.25,47.37)
  BOTTOM w0.127: RJ26.1 77,47.62 v1(77.25,47.37) 77.25,46.52 R330.1
VCAP_VBBLDO_DSP: length 5
  TOP w0.254: U27.F8 v3(53.1,77.17)
  BOTTOM w0.381: v3(53.1,77.17) 53.1,74.73 53.39,74.45 C388.1
VCAP_VBBLDO_GPU: length 5.7
  TOP w0.254: U27.T7 v3(53.75,83.67)
  BOTTOM w0.254: 54.89,84.05 54.74,84.2 54.29,84.2 v3(53.75,83.67)
  BOTTOM w0.381: C329.1 54.89,84.05
VCAP_VBBLDO_IVA: length 6.4
  TOP w0.254: U27.G14 48.88,78.14 v3(49.2,77.82)
  LY4 w0.254: v2(47.5,73.3) 49.02,74.8 49.02,77.64 v3(49.2,77.82)
  BOTTOM w0.305: v2(47.5,73.3) 47.5,72.77 C395.1
VCAP_VBBLDO_MPU: length 5.3
  TOP w0.254: U27.F17 v3(46.6,77.17)
  BOTTOM w0.254: v3(46.6,77.17) 46.6,74.04 45.8,73.23 C394.1
VCAP_VDDRAM_CORE1: length 6.3
  TOP w0.102: 44.12,84.32 44.58,84.32 ; v3(44,84.97) 44.01,84.43
  TOP w0.152: 44.01,84.43 44.12,84.32
  TOP w0.254: 44.58,84.32 U27.U20
  BOTTOM w0.254: C322.1 41.18,84.94 41.59,84.53 43.56,84.53 v3(44,84.97)
VCAP_VDDRAM_CORE3: length 7
  TOP w0.102: 54.31,80.42 53.84,80.42 ; v3(54.4,81.07) 54.41,80.52
  TOP w0.203: 54.41,80.52 54.31,80.42
  TOP w0.254: 53.84,80.42 53.66,80.27 U27.K7
  BOTTOM w0.203: 57.28,80.64 55.88,80.64 55.46,81.07 v3(54.4,81.07)
  BOTTOM w0.254: C358.1 57.78,80.14 57.28,80.64
VCAP_VDDRAM_CORE4: length 14.7
  TOP w0.305: U27.G19 45.63,78.14 v3(45.95,77.82)
  BOTTOM w0.254: C412.1 44.32,66.04 44.03,66.34 v1(44.03,66.76)
  BOTTOM w0.305: v1(44.03,66.76) 43.98,66.76 42.67,68.07 42.67,70.36 43.81,71.5 43.81,73.03 45.59,74.8 45.59,77.46 v3(45.95,77.82)
VCAP_VDDRAM_DSP: length 7.9
  TOP w0.102: 53.1,81.6 53.1,81.07
  TOP w0.254: 53.1,81.07 U27.L7 ; 53.1,81.6 53.1,81.72 v3(53.1,81.72)
  BOTTOM w0.254: 56.89,82.05 54.1,82.05 53.99,82.15 53.54,82.15 v3(53.1,81.72)
  BOTTOM w0.406: C334.1 57.78,81.16 56.89,82.05
VCAP_VDDRAM_GPU: length 5.6
  TOP w0.254: U27.V7 v3(53.75,85.62)
  BOTTOM w0.381: v3(53.75,85.62) 54.24,86.11 55.49,86.11 55.62,86.23 C320.1
VCAP_VDDRAM_IVA: length 12.9
  TOP w0.254: U27.G12 v3(49.85,77.82)
  LY3 w0.305: v1(51.31,67.08) 51.31,67.54 50.65,68.2 50.65,73.44 49.4,74.68 49.4,75.02 49.4,75.03 49.4,76.83 49.85,77.29 v3(49.85,77.82)
  BOTTOM w0.254: 51.29,67.04 51.31,67.06 51.31,67.08
  BOTTOM w0.406: 51.31,67.08 v1(51.31,67.08) ; C426.1 51.29,67.04
VCAP_VDDRAM_MPU: length 6.5
  TOP w0.254: U27.G18 v3(46.6,77.82)
  BOTTOM w0.254: C374.1 46.1,74.17 46.1,77.31 v3(46.6,77.82)
VDA_COREGMACVID_FIL1V8: length 20.7
  TOP w0.254: U27.L9 v3(51.8,81.07) U27.L10 v3(51.8,80.42) U27.K10
  BOTTOM w0.254: 56.73,80.18 56.64,80.26 55.5,80.26 55.35,80.41
  BOTTOM w0.305: v3(51.8,81.07) v3(51.8,80.42) 55.35,80.41
  BOTTOM w0.381: C372.1 67.15,78.5 E5.3 ; C359.1 57.53,79.38 56.73,80.18
  BOTTOM w0.406: E5.3 66.27,78.59 66.04,78.36 62.74,78.36 C359.1
VDA_CSI_FIL1V8: length 16.3
  TOP w0.254: U27.T6 v3(54.4,83.67)
  BOTTOM w0.305: v3(54.4,83.67) 54.76,83.32 58.04,83.32
  BOTTOM w0.381: 58.04,83.32 61.74,83.32 62.36,82.69 C333.1 62.99,83.19 65.95,83.19 66.48,83.72 E3.3 69.07,83.72 C324.1
VDA_DDRDBGGPUPER_FIL1V8: length 22.8
  TOP w0.254: U27.M10 v3(51.8,81.72) U27.N10 v3(51.8,82.37) U27.N9
  LY3 w0.203: v3(51.8,81.72) 52.38,81.72 53.27,82.61 57.85,82.61
  LY3 w0.381: v1(68.2,82.58) 65.94,82.58 65.41,82.04 62.99,82.04 62.42,82.61 57.85,82.61
  BOTTOM w0.254: C340.1 v3(51.8,82.37)
  BOTTOM w0.305: v3(51.8,82.37) v3(51.8,81.72)
  BOTTOM w0.406: E4.3 67.89,82.27 v1(68.2,82.58) 68.59,82.18 C343.1
VDA_HDMI_FIL1V8: length 26.9
  TOP w0.254: U27.Y11 v3(50.5,86.27) U27.W11 ; U27.Y15 v3(48.55,86.27) U27.W15
  LY3 w0.508: v3(48.55,86.27) 48.8,86.27 49.36,86.83 50.09,86.83 50.5,86.41 v3(50.5,86.27)
  BOTTOM w0.254: C308.1 v3(48.55,86.27)
  BOTTOM w0.381: v3(50.5,86.27) 50.81,86.58 50.81,86.9 51.55,87.63 52.2,87.63 53.85,89.28 57.91,89.28 60.07,91.44 62.36,91.44 64.22,89.57 E2.3
  BOTTOM w0.508: E2.3 69.2,89.57 C301.1
VDA_MPU_ABE_FIL1V8: length 17.3
  TOP w0.254: U27.K16 v3(47.25,80.42) U27.L16
  LY4 w0.305: 47.25,79.51 47.12,79.38 47.12,77.03 46.99,76.91 46.99,76.2 46.15,75.36
  LY4 w0.381: 47.25,79.51 v3(47.25,80.42) ; v1(41.8,70.12) 46.15,74.47 46.15,75.36
  BOTTOM w0.254: C349.1 47.15,80.52 v3(47.25,80.42)
  BOTTOM w0.406: v1(41.8,70.12) 41.39,69.72 E7.3 41.31,69.13 v1(41.31,68.21) 41.27,68.18 C407.1
VDA_OSC_FIL1V8: length 15.2
  TOP w0.254: U27.Y13 v3(49.85,86.27) U27.W13
  BOTTOM w0.254: v3(49.85,86.27) C309.1 50.29,86.96 50.29,87.3 50.71,87.72
  BOTTOM w0.381: 50.71,87.72 51.18,88.19 51.18,88.77 57.52,95.11 C286.1 58.68,95.11 58.78,95.02 E1.3
VDA_PHY_1V8: length 41.6
  TOP w0.254: U27.Y9 v3(52.45,86.27) U27.Y8 v3(53.1,86.27) U27.W8
  TOP w0.508: v1(70.87,88.14) 70.07,87.34 v1(68.16,87.34)
  BOTTOM w0.305: v3(53.1,86.27) 53.1,86.91 53.75,87.56 C306.1 53.76,87.57 54.36,88.17
  BOTTOM w0.381: E2.1 66.46,87.34 65.91,86.79 65.91,86.74 ; 65.91,86.74 65.91,86.36 66.32,85.95 E3.1 ; 65.91,86.74 62.74,86.74 61.98,87.5 58.55,87.5 58.08,87.97 C302.1 ; v3(53.1,86.27) v3(52.45,86.27)
  BOTTOM w0.508: C302.1 54.65,88.46 54.36,88.17 ; v1(74.3,101.35) 72.9,101.35 69.34,97.79 69.34,95.63 70.87,94.11 v1(70.87,88.14) ; E2.1 v1(68.16,87.34)
VDA_PLL_1V8: length 209.5
  TOP w0.254: v3(44.65,83.67) U27.R20
  LY4 w0.381: v2(39.16,68.47) 39.65,68.96 40.54,68.96 40.8,68.96 42.29,68.96 42.89,68.37 v1(43.57,68.37)
  LY4 w0.508: v1(67.44,101.35) 63.88,101.35 60.96,104.27 10.29,104.27 3.68,97.66 3.68,69.34 4.19,68.83 v1(24.89,68.83)
  BOTTOM w0.254: C331.1 40.2,84.15 44.25,84.15 44.65,83.75 v3(44.65,83.67)
  BOTTOM w0.381: C406.1 39.14,68.45 v2(39.16,68.47) ; C331.1 39.74,83.3 39.37,82.93 37.97,82.93 37.08,82.04 37.08,80.26 35.43,78.61 35.43,73.24 37.85,70.83 37.85,69.47
  BOTTOM w0.406: E6.1 v1(43.57,68.37) ; E7.1 v2(39.16,68.47)
  BOTTOM w0.508: v1(24.89,68.83) 25.53,69.47 37.85,69.47 C406.1 ; v1(67.44,101.35) 62.74,101.35 59.82,98.42 E1.1 61.21,97.26 61.98,96.49 61.98,92.96 64.39,90.55 69.6,90.55 70.1,90.04 70.1,79.96 ; v1(66.17,76.33) 66.19,76.35 E5.1 67.92,76.35 v1(67.94,76.33) 69.34,76.33 70.1,77.09 70.1,79.96 ; 70.1,79.96 v1(67.92,79.96) 67.84,80.04 E4.1 v1(66.29,80.04)
VDA_SDIO_DV: length 84.3
  TOP w0.254: U27.N8 v3(52.45,82.37) U27.P8
  TOP w0.305: v1(71.12,82.17) 70.99,82.04 62.74,82.04 62.23,82.55 60.2,82.55 v1(59.56,81.92) ; U604.5 72.26,96.14 v1(72.39,96.27) ; U604.6 71.76,96.13 v1(71.63,96.27)
  LY4 w0.508: v1(71.63,89.53) 71.69,89.6 73.21,89.6 73.79,90.17 83.6,90.17 84.13,89.64 96.62,89.64 97.16,90.17 103.38,90.17 v1(104.78,88.77)
  BOTTOM w0.254: v3(52.45,82.37) 52.61,82.53 54.16,82.53 54.19,82.55 55.38,82.55 55.5,82.68
  BOTTOM w0.305: v1(104.78,88.77) R410.1 R230.1 R228.1 R226.1 R227.1 R229.1 R231.1
  BOTTOM w0.381: v1(59.56,81.92) 59.31,82.17 C345.1
  BOTTOM w0.406: C345.1 59.18,82.68 55.5,82.68
  BOTTOM w0.508: v1(71.12,82.17) 71.12,87.12 71.63,87.63 v1(71.63,89.53) v1(71.63,96.27) v1(72.39,96.27) 74.55,96.27 75.18,96.9 R605.2
VDA_VIDEO_FIL1V8: length 15.7
  TOP w0.254: U27.L14 v3(48.55,80.42) U27.K14
  BOTTOM w0.254: v3(48.55,80.42) 48.45,80.23 48.45,80.23 48.18,79.96 48.18,79.96 C364.1 47.95,79.32 47.24,78.61 47.24,76.45 47.47,76.22 47.47,74.14 46.61,73.28
  BOTTOM w0.305: 46.61,73.28 46.61,70.66 46.07,70.11 v1(45.8,70.11)
  BOTTOM w0.406: C408.1 45.8,67.26 E6.3 v1(45.8,70.11)
VHDMI_5V0: length 16.5
  TOP w0.203: 41.22,119.52 P1.18 41.22,118.04 v1(41.27,117.98) ; U17.12 47.57,110.67 v1(47.88,110.36)
  LY4 w0.305: v1(47.88,110.36) 47.88,115.57 46.86,116.59 42.67,116.59 v1(41.27,117.98)
  BOTTOM w0.305: C268.1 v1(47.88,110.36)
VIO_3V3: length 184.6
  TOP w0.102: 45.29,80.95 45.31,80.94 45.31,80.54 ; 47.82,77.82 47.34,77.82
  TOP w0.127: 47.34,77.82 47.34,77.82
  TOP w0.203: 45.31,80.54 45.31,80.42 U27.K19 45.39,79.85 v3(45.3,79.77) ; 45.29,80.95 45.29,81.06 U27.M19 ; U17.23 47.57,116.15 v1(47.88,116.46)
  TOP w0.254: U40.11 98.53,51.2 v1(98.55,51.18) ; U27.N19 v3(45.95,81.72) U27.M19 ; U27.M7 v3(53.75,81.72) U27.N7 ; 47.82,77.82 U27.G15 48.49,78.46 U27.H15 ; U27.J19 v3(45.3,79.77) ; U27.U8 v3(53.1,84.32) U27.U7 ; U70.2 v1(111.37,84.33) ; U27.AA10 v3(51.8,86.92) U27.Y10 ; v1(111.25,83.57) 111.25,83.58 111,83.83 U70.1 ; 47.34,77.82 U27.G17 v3(46.6,78.47) U27.H17
  TOP w0.305: C556.1 22.87,55.05 v1(22.87,54.48) U78.22 ; R412.1 v1(111.76,86.36) ; U40.22 95.38,55.61 v1(95.38,56.39) ; v1(97.79,46.74) 98.35,46.74 C212.1 98.35,47.5 v1(97.78,47.5) ; 51.82,77.83 51.8,77.83 U27.G10 ; 51.82,77.83 v3(52.15,77.06) ; 51.82,77.83 U27.G9 ; U31.F9 v1(84.78,66.75) ; U31.F5 v1(79.77,66.75) ; v1(113.41,83.82) 113.41,83.31 C546.1 112.65,83.31 v1(112.65,83.82) ; v1(82.8,52.2) 83.06,52.45 R308.1 ; U31.F6 v1(81.77,66.75) ; U31.F4 v1(78.77,66.75) ; U31.F2 v1(76.77,66.75) ; U31.F8 v1(83.77,66.75) ; v1(89.03,47.62) 88.47,47.62 C189.1 88.47,46.86 v1(89.04,46.86) ; 72.77,36.52 TP600.1 ; TP600.1 73.46,37.21 ; TP600.1 72.77,37.9 ; U31.F7 v1(82.77,66.75) ; U22.8 13.3,108.42 v1(12.95,108.08) ; 47.12,108.58 v1(47.88,108.58) ; 70.23,95.12 v1(70.23,95.89) ; R447.2 v1(55.5,94.11) ; U31.F3 v1(77.77,66.75) ; U79.5 v1(105.41,56.77) ; R71.1 v1(26.92,74.55) ; R27.2 v1(42.42,113.67)
  TOP w0.508: v1(21.93,114.94) 21.97,114.97 C83.1 ; 64.9,71.12 v1(65.91,71.12) C118.1 ; v1(26.67,44.45) 26.67,44.96 L45.2 27.43,45.21 v1(27.43,44.45) ; 17.14,116.71 v1(16.38,116.71) ; U606.3 v1(116.53,104.7) ; C119.1 v1(67.44,71.5) ; C120.1 v1(69.47,71.5)
  LY3 w0.305: v1(26.92,74.55) 30.1,74.55 35.94,80.39 v1(36.32,80.39)
  LY4 w0.305: v1(82.04,95.12) 79.63,95.12 78.61,96.14 73.28,96.14 72.64,95.5 70.61,95.5 v1(70.23,95.89) ; v1(70.48,58.55) 71.25,57.78 72.77,57.78 76.77,53.78 v1(76.77,53.15)
  LY4 w0.508: v3(51.8,86.92) 51.18,87.54 51.18,89.41 50.59,90 v1(50.59,91.82) 50.59,93.51 51.94,94.87 v1(52.7,94.87)
  LY5_PWR w0.305: 72.08,37.21 TP600.1 ; TP600.1 72.77,36.52 ; TP600.1 72.77,37.9 ; TP600.1 73.46,37.21
  BOTTOM w0.254: U52.1 21.56,115.3 v1(21.93,114.94) ; C507.1 v1(95.38,56.39)
  BOTTOM w0.305: P9.34 v1(69.77,111.12) ; R609.1 R610.1 v1(112.01,103) ; v1(79.77,66.75) 79.95,66.93 C435.1 ; v1(68.96,111.12) 68.77,111.31 P9.32 ; R233.2 v1(14.99,112.78) ; 82.69,96.65 82.68,96.64 82.68,95.76 v1(82.04,95.12) ; v1(70.48,111.12) 70.27,111.34 P9.36 ; v1(68.2,111.12) 68.27,111.2 P9.30 ; R344.1 v1(90.17,50.67) ; C508.1 88.79,46.61 v1(89.04,46.86) ; v1(105.41,56.77) C521.1 ; R358.2 R360.2 R365.2 98.17,50.8 v1(98.55,51.18) C511.1 ; C282.1 v1(36.32,80.39) ; v1(22.87,54.48) 22.86,54.48 C557.1 ; R342.2 v1(90.55,47.54) ; v1(84.84,94.87) 84.84,95.38 84.69,95.53 84.69,96.65 ; U54.5 71.37,58.83 71.09,58.55 v1(70.48,58.55) ; v1(74.68,49.91) R310.1 R311.1 ; C267.1 48.13,116.2 v1(47.88,116.46) R212.2 ; 107.95,100.46 R619.1 v1(109.98,100.46) ; 84.19,96.65 v1(84.19,95.25) ; C519.1 98.04,46.48 v1(97.79,46.74) ; R329.1 R328.1 v1(79.12,47.37) ; v1(97.78,47.5) 98.03,47.75 C518.1 ; v3(53.1,84.32) 53.58,84.32 54.36,85.09 C432.1 ; v1(76.77,53.15) 77.22,52.7 R312.1 ; v1(12.95,108.08) 12.45,108.58 C275.2 ; 83.69,96.65 83.69,96.11 83.7,96.1 83.7,95.68 83.68,95.66 83.68,95.62 v1(83.19,95.12) ; 89.04,47.62 v1(89.03,47.62) 88.77,47.88 C509.1 ; R262.2 26.93,74.55 v1(26.92,74.55) ; 83.19,96.65 v1(83.19,95.89) ; R236.2 v1(52.7,94.87) ; v1(84.78,66.75) 84.96,66.93 C437.1 ; R382.1 v1(109.22,64.9) ; R249.1 v1(50.42,120.9) ; 49.4,114.17 R216.1 R215.2 ; R234.2 v1(14.99,111.51) ; R307.1 79.45,50.8 v1(79.77,51.12)
  BOTTOM w0.381: C285.1 v1(52.7,94.87)
  BOTTOM w0.406: C281.1 v1(55.5,94.11) ; v1(50.59,91.82) 50.08,91.31 C296.1
  BOTTOM w0.508: 27.18,55.5 34.92,55.5 36.2,54.23 38.99,54.23 39.37,54.61 39.37,56.9 39.75,57.28 R602.1 ; 116.53,104.7 v1(116.53,104.7) ; 116.53,104.7 116.53,105.47 C641.2 ; 116.53,104.7 116.45,104.78 C632.2 ; C285.1 C284.1 55.42,95.63 C281.1 ; C442.2 v1(70.48,58.55)
  vias: v1(49.15,108.71) v1(50.29,113.67) v1(50.29,112.65) v1(50.29,111.25) v1(50.29,110.24) v1(51.18,109.09) v1(51.44,115.06) v1(73.41,34.8) v1(73.53,35.94) v1(74.04,38.1) v1(74.04,36.96) v1(78.87,70.48) v1(79.88,70.48) v1(80.9,70.48)
VIO_3V3_SD: length 13.5
  TOP w0.254: v1(113.54,91.06) 113.28,91.31 C544.1 ; U70.7 v1(107.83,84.33) ; C545.1 v1(113.54,93.85) ; U70.8 108.09,83.83 v1(107.82,83.57) ; C542.1 v1(113.54,96.39)
  TOP w0.305: v1(113.54,93.85) 113.92,93.47 C540.1 115.19,93.22 C541.1
  BOTTOM w0.254: v1(113.54,93.85) 113.53,93.85 U67.1 ; v1(113.54,91.06) 113.29,91.31 U66.1 ; v1(113.54,96.39) 113.53,96.39 U68.1
  BOTTOM w0.305: P10.4 115.45,93.46 115.06,93.85 v1(113.54,93.85)
VOUT3B_CLK: length 36.2
  TOP w0.127: R445.1 61.85,77.6 62.36,77.09 v1(63.37,77.09)
  LY3 w0.133: v1(93.22,78.32) 90.34,75.44 83.06,75.44 81.53,76.96 63.5,76.96 v1(63.37,77.09)
  BOTTOM w0.127: v1(93.22,78.32) 93.32,78.42 93.32,80.64
VOUT3B_D0: length 45.4
  TOP w0.127: SW1.12 v1(81.03,78.74) ; v1(81.03,76.33) 80.9,76.45 68.45,76.45 68.16,76.75 63.79,76.75 63.72,76.67 60.74,76.67 59.92,77.49 U27.F1
  LY3 w0.133: v1(94.32,79.79) 94.32,79.08 93.98,78.74 92.96,78.74 91.42,77.19 89.8,77.19 89.32,76.71 83.06,76.71 v1(81.03,78.74)
  BOTTOM w0.127: 94.32,80.64 v1(94.32,79.79) ; R259.1 v1(81.03,78.74) v1(81.03,76.33)
